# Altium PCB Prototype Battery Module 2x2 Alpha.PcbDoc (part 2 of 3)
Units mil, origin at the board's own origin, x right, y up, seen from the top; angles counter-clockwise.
Board outline 659.45 x 1614.17 mil, 6 copper layers (Component Side, Ground Plane (GND), Inner Layer 1, Inner Layer 2, Power Plane (VCC), Solder Side), stack 51.068 mil thick; 192 components, 101 nets, 859 pads, 497 vias.
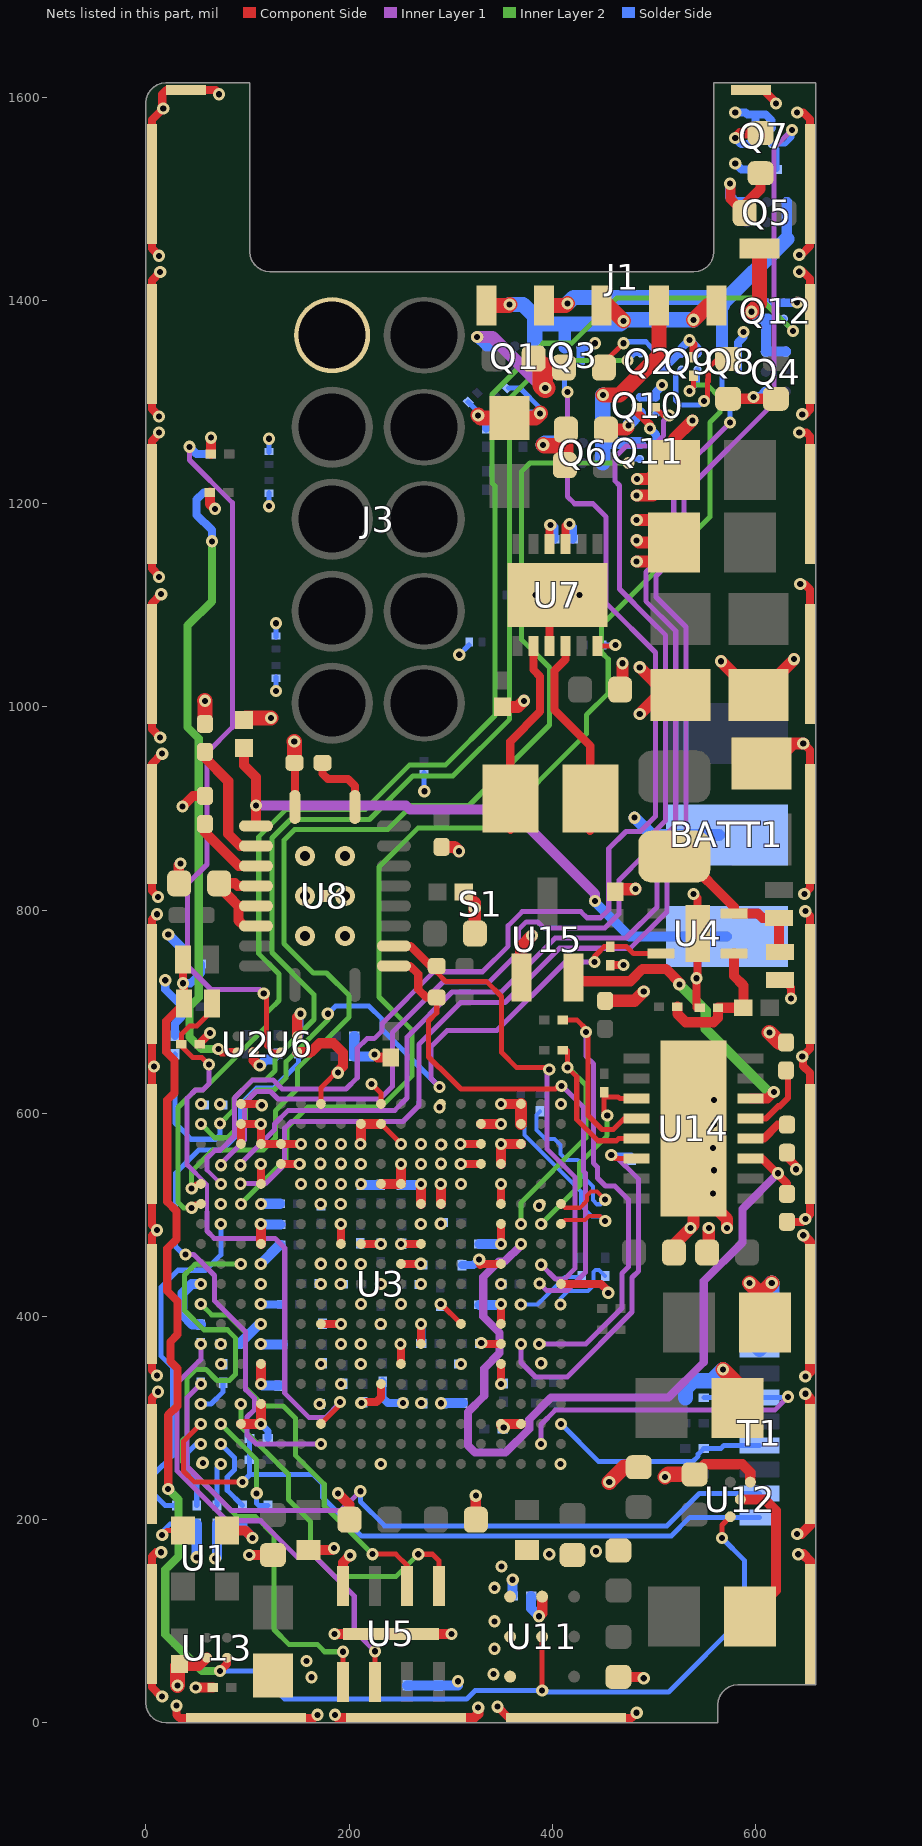
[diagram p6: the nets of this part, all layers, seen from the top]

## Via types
v1: diameter 12, hole 6, Component Side to Solder Side, tented both sides, 490 vias
v2: diameter 19.68, hole 10, Component Side to Solder Side, 6 vias
v3: diameter 12, hole 6, Component Side to Solder Side, 1 vias

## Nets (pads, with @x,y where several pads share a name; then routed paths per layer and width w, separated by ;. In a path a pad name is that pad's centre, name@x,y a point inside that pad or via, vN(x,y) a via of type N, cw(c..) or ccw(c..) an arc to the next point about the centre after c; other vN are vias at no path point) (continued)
CH_STAT1: R42.2 U3.K2 U8.2 | length 520.8
  Component Side w5: R42.2@286.22,714 286.22,699 278,690.78 278,655.42 288.41,645.01 288.99,645.01 310,624 403,624 405,626 409,626 v1(409,627)
  Component Side w8: U8.2@244.09,745.08 259.92,745.08 268,737 268,722 276,714 R42.2@286.22,714
  Inner Layer 1 w5: v1(387.49,432.51) 394.5,425.5 414.73,425.5 432.5,443.27 432.5,541.27 430.5,543.27 430.5,606.35 409.85,627 v1(409,627)
CH_STAT2: R40.2 U3.L2 U8.3 | length 487.9
  Component Side w5: R40.2@286.22,745 286.22,738.78 295.37,729.63 335.37,729.63 350,715 350,660 365,645 v1@395,645
  Component Side w8: U8.3@244.09,764.77 260.23,764.77 280,745 R40.2@286.22,745
  Inner Layer 1 w5: v1(389,451) 403,437 412.09,437 422.5,447.41 422.5,537.12 394.93,564.7 394.93,640.93 v1(397,643)
CLK_19P2MHZ: R52.2 U3.N18 | length 348.6
  Solder Side w5: 23,214.06 18.93,214.06 ; R52.2@30,214.06 R52.2@30,214.06 18.93,214.06 ; v1(73.7,491.14) 73.7,460.7 58.59,445.59 31.59,445.59 15,429 15,361 26,350 26,263 8.41,245.41 8.41,224.58 18.93,214.06
DETECT_RX: R35.2 U3.B13 | length 575.6
  Inner Layer 1 w5: v1(39,461) 47,461 67.52,440.48 67.52,415.48 98,385 98,327.95 ; 98.98,327.48 106.89,319.57 106.89,308.38 99.57,301.07 99.57,283.43 108.32,274.68 v1(172.2,274.68)
  Solder Side w5: 29,479 29,489 ; v1(39,461) 37,461 29,469 29,489 ; R35.2@150,658.94 150,649 126,625 117,625 109,625 93,609 93,582 75,564 52,564 30,542 29,541 29,489
DISC_STAT1_N: R53.2 U3.G3 U14.14 | length 371.9
  Component Side w5: v1@461.5,555.5 464.59,555.5 ; 464.62,555.47 U14.14@482.9,555.47
  Inner Layer 1 w5: v1(369.06,373.11) 369.06,354.85 383.41,340.5 414.64,340.5 478.5,404.36 478.5,438.36 485,444.86 485,535.09 461.09,559 v1(458,559)
  Solder Side w5: v1(458,559) 477.78,559 R53.2@478,558.78
DISC_STAT2_N: R54.2 U3.N2 U14.11 | length 186
  Component Side w5: v1(454,598) 451,601 451,616.22 464.78,616.22 466.47,614.53 U14.11@482.9,614.53
  Inner Layer 2 w5: v1(389,491) 427,529 427,551 454,578 v1(454,598)
DISC_WARN1_N: R50.2 U3.N3 U14.13 | length 332.2
  Component Side w5: R50.2@414.78,662 414.78,645.22 424,636 424,594 445,573 463.22,573 465.38,575.16 U14.13@482.9,575.16
  Inner Layer 2 w5: v1(369.06,491.22) 369.06,512.06 433,576 433,628 414.78,646.22 414,646.22 414,645.26 414.26,645 v1(415,645)
DISC_WARN2_N: R51.2 U3.G2 U14.12 | length 562.3
  Component Side w5: v1(387,373) 388.63,373 U3.G2@388.74,373.11 ; R51.2@414.78,692 424,692 434,682 v1@434,681 ; v1(433,680) v1@434,681 ; U14.12@482.9,594.84 470.84,594.84 460,584 448.91,584 435,597.91 435,680 v1@434,681
  Inner Layer 1 w5: v1(387,373) 433,373 468.5,408.5 468.5,442.5 475,449 475,515 461.5,528.5 452.41,528.5 444.5,536.41 444.5,547 440.5,551 440.5,648.73 433,656.23 v1(433,680)
DONE: R34.1 T1.8 U3.E19 | length 786.8
  Inner Layer 1 w5: 40.52,319.57 40.52,307 ; v1(54.09,333.74) 40.52,320.16 40.52,307 ; v1(211,228) 192,209 83.91,209 40.52,252.39 40.52,307
  Solder Side w5: v1(211,228) 211,218 235,194 245.91,194 310,194 ; 344,194 310,194 ; 559.94,225.94 575,225.94 ; T1.8@593.74,225.94 578,225.94 ; T1.8@604,225.94 578,225.94 ; 310,194 512.86,194 544.8,225.94 575,225.94 ; 575,225.94 578,225.94
EPM_HBA_N: Q3.1 U3.R18 | length 1207.3
  Inner Layer 1 w4: 60.2,544.17 v1(73.78,530.59)
  Inner Layer 1 w5: 60.2,544.17 60.2,555.79 68.11,563.7 73.06,563.7 87.17,577.81 87.17,615.08 105.09,633 125.14,633 134.14,624 197,624 208,635 208,664 217.5,673.5 224.59,673.5 232.5,681.41 232.5,688.5 283.32,739.32 331.32,739.32 356.5,764.5 356.5,784.73 370.27,798.5 428,798.5 434,792.5 447.5,792.5 455.5,800.5 455.5,860.59 472.41,877.5 486.59,877.5 501.5,892.41 501.5,1053.5 453,1102 453,1187 440,1200 422,1200 415,1207 v1(415,1310)
  Solder Side w5: Q3.1@412.13,1338.13 412.13,1312.87 v1(415,1310)
EPM_HBA_P: Q2.1 R59.1 U3.V18 | length 1221.6
  Inner Layer 2 w5: v1(73,590) 73.09,590 86.5,603.41 86.5,614.41 105.09,633 118,633 127,642 127,653.91 165.5,692.41 165.5,716.79 124,758.29 124,871 142.28,889.28 220,889.28 262.72,932 302,932 358,988 358,1303.91 395.09,1341 v1(474,1341)
  Solder Side w5: R59.1@28.54,658.27 28.54,590.46 44.5,574.5 68.5,574.5 73,579 v1(73,590) ; v1(474,1341) 480.87,1347.87 Q2.1@487.13,1347.87
EPM_HBB_N: Q8.1 U3.T17 | length 1141.1
  Inner Layer 1 w5: v1(93,549) 93,550.3 126.57,583.87 126.57,589.52 140.05,603 245,603 257,615 257,675 301.32,719.32 349.68,719.32 402.86,772.5 472.59,772.5 503,802.91 503,865.62 521.5,884.12 521.5,1074.64 492,1104.14 492,1132.91 496.5,1137.41 496.5,1148.98 519.52,1172 519.52,1224.52 v1(575,1280)
  Solder Side w5: Q8.1@567.13,1332.13 567.13,1299.87 575,1292 v1(575,1280)
EPM_HBB_P: Q7.1 R60.1 U3.R17 | length 1488.8
  Inner Layer 1 w5: v1(93.19,530.74) 117.74,530.74 136.57,549.57 136.57,585.38 143.19,592 253,592 268.78,607.78 268.78,667.92 309.86,709 353.5,709 407,762.5 476.73,762.5 513,798.77 513,857 531.5,875.5 531.5,1078.78 502.14,1108.14 502.14,1128.91 506.5,1133.27 506.5,1144.84 529.52,1167.86 529.52,1210.52 618,1299 618,1550 v1(636,1568)
  Solder Side w5: R60.1@621.06,1529 621.06,1548.94 Q7.1@615.87,1554.13 629.13,1554.13 636,1561 v1(636,1568)
EPM_HBC_N: Q11.1 U3.R19 | length 1171.8
  Component Side w5: v1(45,526) 49.59,530.59 53.59,530.59 U3.R19@54.09,530.59
  Inner Layer 2 w5: v1(45,526) 45,543 66,564 115.57,564 127.5,575.93 127.5,602.5 149,624 149,634 149,643.86 200,694.86 200,716 177.78,738.22 164.78,738.22 136,767 136,868.86 146.42,879.28 238,879.28 261.72,903 318,903 397.28,982.28 397.28,1038.72 369.85,1066.15 369.85,1231.85 378,1240 v1(475,1240)
  Solder Side w5: v1(475,1240) 479.13,1244.13 Q11.1@486.13,1244.13
EPM_HBC_P: Q10.1 R61.1 U3.T18 | length 1211.8
  Component Side w5: R61.1@501.06,1295 509.06,1287 v1(515,1287)
  Inner Layer 1 w5: v1(74,549) 74,549.9 73.7,550.2 97.17,573.67 97.17,610.26 108.41,621.5 115,621.5 ; 120.48,621.5 115,621.5 ; 266.42,703.42 274,711 ; 386.59,787.5 385.59,788.5 ; 466,1187 466,1170 ; 492,1090 496,1086 ; v1(515,1287) 509.52,1281.52 509.52,1267 499.52,1257 472.91,1257 461.5,1245.59 461.5,1222.5 466,1218 466,1170 ; 115,621.5 122.5,621.5 130,614 230,614 242.5,626.5 242.5,679.5 274,711 ; 274,711 292.32,729.32 338,729.32 366.5,757.82 366.5,780.59 374.41,788.5 385.59,788.5 ; 385.59,788.5 391.59,782.5 451.64,782.5 465.5,796.36 465.5,829.5 491,855 491,867.77 511.5,888.27 511.5,1070.5 496,1086 ; 466,1170 466,1116 496,1086
  Solder Side w5: Q10.1@501.87,1289.13 512.87,1289.13 v1(515,1287)
EPM_HBD_N: Q12.1 U3.P19 | length 1407.7
  Component Side w5: v1(45,507) 48.91,510.91 U3.P19@54.09,510.91
  Inner Layer 2 w5: v1(45,507) 37,507 31.5,512.5 31.5,605.83 48.5,622.83 55.92,622.83 118.5,685.41 118.5,698.59 123.75,703.84 ; 121.45,701.55 123.75,703.84 ; v1(637,1370) 604.5,1402.5 463.5,1402.5 419,1358 391,1358 340.5,1307.5 340.5,1220.46 343.5,1217.46 343.5,991.5 295,943 259.58,943 215.86,899.28 138.14,899.28 111,872.14 111,757.15 131,737.15 131,711 126.5,706.5 126.41,706.5 123.75,703.84
  Solder Side w5: Q12.1@627.87,1382.13 627.87,1379.13 v1(637,1370)
EPM_HBD_P: Q9.1 R62.1 U3.P17 | length 1183.1
  Component Side w5: v1(535,1311) 539,1315 R62.1@539,1325.94
  Inner Layer 2 w5: v1(93.46,510.91) 137.84,555.28 137.84,569.84 ; 139,571 139,586 159,606 231,606 262,637 262,681.91 229.5,714.41 229.5,842.5 268,881 341,881 433.5,973.5 433.5,992 455,1013.5 455,1047 448.5,1053.5 448.5,1080.5 555,1187 555,1280 565,1290 565,1304.46 552.46,1317 548,1317 541,1317 v1(535,1311)
  Solder Side w5: v1(535,1311) 542.87,1318.87 Q9.1@542.87,1332.13
EPM_REG_EN: R9.1 U3.V19 U4.6 | length 689.8
  Component Side w5: v1(441.43,749) 441.43,754.43 444.36,757.36 451.06,764.06 R9.1@457,764.06 472.94,764.06 479.69,757.31 U4.6@507.17,757.31
  Inner Layer 1 w5: v1(288.95,625.95) 280.5,634.41 280.5,665.5 296.5,681.5 324,681.5 ; 314.41,681.5 324,681.5 ; v1@440,749 v1(441.43,749) 412.91,749 345.41,681.5 324,681.5
  Inner Layer 2 w5: v1(54.09,589.65) 67.74,576 80,576 98,594 98,611.77 109.23,623 126,623 138,635 138,643 ; 138,646.77 138,643 ; v1(179,698) 179,691.77 138,650.77 138,643
  Solder Side w5: v1(179,698) 186.5,705.5 219.59,705.5 232.5,692.59 ; 232.5,690.5 232.5,692.59 ; v1(288.95,625.95) 232.5,682.41 232.5,692.59
EPMA: J1.0 J1.2 J1.4 Q1.4 Q1.5 Q3.4 | length 343.1
  Component Side w15: J1.0@335,1395 357,1395 v1(358,1396) ; J1.2@448.39,1395 455,1395 v1(470,1380) ; v1(539,1381) 553,1395 J1.4@561.77,1395 J1.4@561.5,1394.73
  Solder Side w12: 412,1377 412.13,1376.87 Q3.4@412.13,1353.87
  Solder Side w15: v1(358,1396) 371,1396 382.69,1384.31 ; Q1.4@382.69,1335.16 Q1.5@382.69,1354.84 382.69,1384.31 ; v1(539,1381) 471,1381 v1(470,1380) 467,1377 412,1377 390,1377 382.69,1384.31
EPMB: J1.1 Q5.4 Q5.5 Q8.4 | length 357.9
  Component Side w15: J1.1@391.69,1395 413,1395 v1(415,1397)
  Solder Side w10: 630.69,1460.56 Q5.4@630.69,1477.16 Q5.5@630.69,1496.84
  Solder Side w12: Q8.4@567.13,1347.87 567.13,1395
  Solder Side w15: v1(415,1397) 421,1403 561.13,1403 567.13,1397 ; 566.13,1396 567.13,1395 567.13,1397 ; 630.69,1460.56 567.13,1397
EPMC: J1.3 Q6.4 Q6.5 Q11.4 | length 223.7
  Component Side w15: v1(450,1307) 466.16,1307 505.08,1345.92 J1.3@505.08,1395
  Solder Side w12: Q6.5@449.72,1259.87 Q11.4@486.13,1259.87
  Solder Side w15: Q6.4@449.69,1240.16 Q6.5@449.69,1259.84 449.69,1306.69 v1(450,1307)
EPMD: J1.5 Q4.4 Q4.5 Q12.4 | length 137.2
  Component Side w15: v1(596,1389) 604,1397 J1.5@604,1451
  Solder Side w10: v1(596,1389) 602.87,1382.13 Q12.4@612.13,1382.13 610.16,1380.16 Q4.5@610.16,1349.69 Q4.4@629.84,1349.69
EXO_DETECT_RX: R10.2 U6.A1 | length 731
  Component Side w5: v1(116,718) 118.5,715.5 118.5,699 ; 118.5,703.5 118.5,696 118.5,666.5 124.87,660.13 U6.A1@133.13,660.13
  Inner Layer 1 w5: v1(42.94,1256) 42.94,1243 85,1200.94 85,980 60,955 60,845 41,826 41,745 64,722 112,722 v1(116,718)
  Solder Side w8: v1(42.94,1256) 49.94,1249 R10.2@63.89,1249
EXO_WAKE_RX: R8.2 U2.A1 | length 633.5
  Component Side w8: v1(71.22,663.22) 74.32,660.13 U2.A1@90.13,660.13
  Inner Layer 2 w8: 43,682 43,675 ; 52,666 54.78,663.22 ; v1(64.94,1163) 64.94,1103.94 41,1080 41,980 52,969 52,852 52,714 43,705 43,675 ; v1(71.22,663.22) 54.78,663.22 ; 43,675 54.78,663.22
  Solder Side w8: R8.2@62.89,1211 56.95,1211 49.94,1204 49.94,1189 64.94,1174 v1(64.94,1163)
GND: BATT1.2 C1.1 C2.1 C3.1 C4.1 C5.1 C6.1 C7.1 C8.1 C9.1 C11.1 C12.2 C13.2 C14.2 C15.2 C16.1 C17.2 C18.1 C19.1 C20.1 C21.1 C22.1 C23.1 C24.1 C25.1 C26.1 C27.1 C28.1 C29.1 C30.1 C31.1 C32.1 C33.1 C34.1 C35.1 C36.1 C37.1 C38.1 C39.1 C40.1 C41.1 C42.1 C43.1 C44.1 C45.1 C46.1 C47.1 C48.1 C49.1 C50.1 C51.1 C52.1 C53.1 C57.1 C58.1 C59.1 C60.1 C61.1 C62.1 C63.1 C64.1 C65.1 C66.1 C67.1 C68.1 C69.1 C70.1 C71.1 C72.1 C73.1 C77.1 C78.1 C81.1 C82.1 C94.1 C95.1 D2.1 J3.10 Q2.2 Q2.3 Q3.2 Q3.3 Q7.2 Q7.3 Q8.2 Q8.3 Q9.2 Q9.3 Q10.2 Q10.3 Q11.2 Q11.3 Q12.2 Q12.3 R1.2 R2.1 R5.2 R6.2 R9.2 R14.2 R15.2 R20.1 R21.2 R23.2 R24.2 R25.2 R30.2 R31.2 R32.2 R33.2 R36.2 R37.2 R41.1 R43.1 R45.1 R46.2 R47.2 R48.2 R49.2 R55.2 R56.2 R57.2 R59.2 R60.2 R61.2 R62.2 S1.S T1.1 TVS1.2 TVS2.2 TVS3.2 TVS4.2 TVS5.2 TVS6.2 TVS7.2 TVS8.2 TVS9.2 U1.2 U2.B1 U3.A1 U3.A10 U3.A19 U3.C3 U3.C4 U3.C16 U3.C17 U3.D16 U3.E4 U3.E10 U3.E12 U3.E16 U3.F2 U3.F4 U3.F6 U3.F9 U3.F11 U3.F13 U3.F16 U3.F18 U3.G4 U3.G8 U3.G9 U3.G11 U3.G12 U3.G16 U3.H4 U3.H6 U3.H8 U3.H10 U3.H12 U3.H13 U3.H16 U3.J4 U3.J7 U3.J9 U3.J11 U3.J16 U3.K1 U3.K4 U3.K8 U3.K10 U3.K12 U3.K13 U3.K16 U3.K19 U3.L4 U3.L8 U3.L9 U3.L11 U3.L12 U3.L13 U3.L16 U3.M4 U3.M8 U3.M9 U3.M10 U3.M11 U3.M12 U3.M16 U3.N4 U3.N7 U3.N8 U3.N12 U3.N16 U3.P2 U3.P4 U3.P7 U3.P8 U3.P12 U3.P13 U3.P16 U3.P18 U3.R4 U3.R6 U3.R7 U3.R8 U3.R9 U3.R10 U3.R11 U3.R12 U3.R13 U3.R14 U3.R16 U3.T4 U3.T5 U3.T6 U3.T7 U3.T8 U3.T9 U3.T11 U3.T12 U3.T13 U3.T14 U3.T15 U3.T16 U3.U3 U3.U4 U3.U5 U3.U6 U3.U7 U3.U8 U3.U9 U3.U11 U3.U12 U3.U13 U3.U14 U3.U15 U3.U16 U3.U17 U3.V3 U3.V4 U3.V5 U3.V10 U3.V11 U3.V16 U3.V17 U3.W1 U3.W3 U3.W4 U3.W7 U3.W10 U3.W13 U3.W16 U3.W17 U3.W19 U4.7 U5.4 U5.9 U6.B1 U7.3 U7.9 U7.13 U8.11 U8.21 U11.C1 U11.C2 U11.C3 U12.A3 U13.B1 U14.17 U15.1 | length 8140.9
  Component Side w5: U3.W13@172.2,609.33 172.2,625.2 172.5,625.5 172.59,625.5 180.5,633.41 180.5,633.5 187,640 v1(189,640) ; v1(222,629) 231.26,619.74 U3.W10@231.26,609.33 ; U3.V10@231.26,589.65 v1(250.94,569.96) ; U3.J7@290.39,412.4 U3.H6@310,392.8
  Component Side w7: U3.F18@73.78,353.43 v1(74,353.2)
  Component Side w8: S1.S@5.91,254.92 5.91,319.91 v1(12,326) v1@13,326 ; v1(8,646) v1@8,647 ; v1(11,796) 5.91,790.91 S1.S@5.91,727.36 5.91,662 ; v1@12,342 v1(11,342) 5.91,347.09 S1.S@5.91,412.4 5.91,479.91 v1(11,485) 5.91,490.09 S1.S@5.91,569.88 5.91,644.91 v1@8,647 ; v1(12,813) 5.91,819.09 S1.S@5.91,884.84 5.91,943.91 v1(16,954) ; v1(13,1128) 13,1129 5.91,1136.09 S1.S@5.91,1199.8 5.91,1261.91 13,1269 v1(13,1270) ; v1(13,1286) 5.91,1293.09 S1.S@5.91,1357.28 5.91,1419.91 v1(14,1428) v1@14,1430 ; v1(13,1444) 5.91,1451.09 S1.S@5.91,1514.76 5.91,1577.91 v1(17,1589) 16,1590 16,1603 20.28,1607.28 S1.S@39.37,1607.28 68.72,1607.28 72,1604 v1(72,1603) ; v1(14,970) 5.91,978.09 S1.S@5.91,1042.32 5.91,1101.91 v1(15,1111) ; v1(15,168) 10,168 5.91,163.91 S1.S@5.91,97.44 5.91,35.09 15,26 v1(16,26) ; v1@29,17 v1(30,17) 30,8 33.08,4.92 S1.S@98.43,4.92 165.92,4.92 v1(169,8) ; R41.1@53.06,668 53.06,669.06 v1(63,679) ; U3.U17@93.46,569.96 U3.V17@93.46,589.65 U3.V16@113.15,589.65 U3.U16@113.15,569.96 U3.U15@132.83,569.96 v1(152.52,569.96) ; U3.W17@93.46,609.33 U3.W16@113.15,609.33 114,608.48 v1(114,608) ; U3.R16@113.15,530.59 U3.T16@113.15,550.28 ; U3.T15@132.83,550.28 U3.T14@152.52,550.28 ; R46.2@146.22,945 146.65,944.57 U8.11@146.65,901.58 ; U3.H13@172.2,392.8 191.79,392.8 v1(191.87,392.72) ; v1(191.81,491.22) 191.89,491.15 U3.M12@191.89,471.54 ; U3.M11@211.57,471.54 231.07,471.54 v1(231.17,471.44) ; v1(212,314.94) 213.06,316 227,316 231.26,320.26 U3.E10@231.26,333.74 ; v1(250.69,373.03) 250.94,372.77 U3.F9@250.94,353.43 ; U3.L9@250.94,451.85 270.5,451.85 v1(270.55,451.9) ; v1(250.94,471.54) U3.M8@270.63,471.54 ; U3.G8@270.63,373.11 v1(270.63,392.8) ; v1(290.13,412.4) U3.J7@290.39,412.4 ; U3.T6@310,550.28 U3.T5@329.69,550.28 ; U3.U6@310,569.96 U3.U5@329.69,569.96 ; v1@328,453 v1(328,456) ; v1@329,451 329.85,451.85 U3.L4@349.37,451.85 ; v1(330,374) 330.89,373.11 U3.G4@349.37,373.11 ; v1(346,16) 357.08,4.92 S1.S@413.39,4.92 477.92,4.92 v1(483,10) ; v1(349.37,333.74) U3.F4@349.37,353.43 ; U3.H4@349.37,392.8 v1(349.37,412.48) ; v1(349.37,471.54) U3.N4@349.37,491.22 ; U3.P4@349.37,510.91 v1(349.37,530.59) ; U7.3@397.13,1059.8 397.13,1102.13 U7.13@405,1110 ; U3.K1@408.43,432.17 447.83,432.17 455,425 v1(455,423.33) ; U7.9@412.87,1160.2 413,1160.32 413,1178 415,1180 v1(417,1180) ; R9.2@457,745.94 469.94,745.94 v1(470,746) ; R61.2@482.94,1295 482.94,1290.93 492.21,1281.67 492.33,1281.67 496.02,1277.98 v1(496.02,1274.02) ; v1(535,1361) 539,1357 R62.2@539,1344.06 ; v1(539,816) 543,812 U4.7@543,777 543,735 v1@542,734 ; R14.2@541.94,704 541.94,733.94 v1@542,734 ; v1(542,733) v1@542,734 ; S1.S@595.47,1607.28 607.72,1607.28 620,1595 v1(620,1594) ; D2.1@624,731.22 627.78,731.22 635,724 v1(635,713) ; R55.2@631,493.22 646.22,493.22 v1(649,496) 653.54,500.54 S1.S@653.54,569.88 653.54,640 646.87,646.67 646.87,655.13 v1(646,656) 653.54,663.54 S1.S@653.54,727.36 653.54,794.46 v1(649,799) ; R56.2@631,561.22 631,557 640,548 v1(640,545) ; v1(641,1585) 647,1585 653.54,1578.46 S1.S@653.54,1514.76 653.54,1453.54 645,1445 v1(643,1445) ; v1(643,1270) 650,1270 653.54,1266.46 S1.S@653.54,1199.8 ; v1(643,1428.35) 646.65,1428.35 653.54,1421.46 S1.S@653.54,1357.28 653.54,1292.54 649,1288 v1(646,1288) ; v1(644,1121) 648,1121 653.54,1115.46 S1.S@653.54,1042.32 ; v1(647,964) 653.54,957.46 S1.S@653.54,884.84 653.54,821.54 v1(648,816) ; 5.91,662 5.91,648.91 6,649 v1@8,647 ; 5.91,662 5.91,649.09 v1@8,647
  Component Side w10: C57.1@31,56.01 52.01,56.01 U13.B1@60.16,64.16 ; C43.1@32.72,826.4 32.32,826.8 32.32,844.32 v1(34,846) ; v1(36,902) 46.4,912.4 R36.2@58.07,912.4 ; v1(49,35) C94.1@65.94,35 ; R15.2@62.89,1211 62.89,1200.05 v1(67.94,1195) ; R31.2@63.89,1249 63.89,1264.94 v1(63.94,1265) ; U1.2@79.65,189.56 97.44,189.56 v1(105,182) ; U3.C17@93.46,294.37 U3.C16@113.15,294.37 U3.D16@113.15,314.06 ; v1(101.69,165.32) C60.1@125,165.32 ; U2.B1@105.87,660.13 105.87,652.13 111,647 v1(112,647) ; v1(113.15,333.74) U3.F16@113.15,353.43 ; U3.M16@113.15,471.54 U3.N16@113.15,491.22 ; U6.B1@148.87,660.13 162.13,660.13 171.04,669.04 184.63,669.04 194,659.67 194,646.41 v1@187.29,639.71 ; C16.1@160,170.32 v1@183.32,170.32 ; v1(185.6,87.6) U5.9@241.14,87.6 v1(300.6,87.6) ; v1(186,8) 189.08,4.92 S1.S@255.91,4.92 322.92,4.92 327,9 v1(327,15) ; v1(189,226) 200.32,214.68 C61.1@200.32,200 ; U5.4@193.9,134.84 193.9,157.9 v1(201,165) ; U3.U11@211.57,569.96 U3.V11@211.57,589.65 U3.V10@231.26,589.65 ; v1(225,658) 227.99,655.01 C45.1@241,655.01 ; U3.R10@231.26,530.59 U3.R9@250.94,530.59 v1(250.94,550.28) ; v1(270.59,530.47) 270.63,530.43 U3.P8@270.63,510.91 ; v1(290.17,530.44) 290.32,530.29 U3.P7@290.32,510.91 ; C72.1@324.69,200 v1(324.69,223.68) ; U3.V5@329.69,589.65 v1(349.37,589.65) ; U3.T4@349.37,550.28 v1(349.37,569.96) U3.U3@369.06,569.96 ; v1(349.37,609.33) U3.W3@369.06,609.33 ; v1(352.2,290.6) 349.37,293.43 U3.C4@349.37,294.37 U3.C3@369.06,294.37 ; U3.F2@388.17,354 U3.F2@388.74,353.43 ; C41.1@465,45.32 488.69,45.32 v1(490,44) ; C81.1@540,244.68 549.86,254.55 587.06,254.55 594.84,246.77 U12.A3@594.84,237.05 ; v1(641,186) 645,186 653.54,194.54 S1.S@653.54,254.92 653.54,319.46 v1(649,324) ; v1(642,166) 647,166 653.54,159.46 S1.S@653.54,97.44 ; v1(647,480) 653.54,473.46 ; v1(649,341) 653.54,345.54 S1.S@653.54,412.4 653.54,473.46 ; 653.54,472.46 653.54,473.46
  Component Side w12: R48.2@291,862.22 303.78,862.22 v1(308,858) ; C46.1@312.99,818 323.69,807.31 v1(323.69,802) C42.1@323.69,777 ; C77.1@351,1000.01 366.01,1000.01 v1(372,1006) ; U3.V3@369.06,589.65 U3.W3@369.06,609.33 ; U15.1@369.41,733.6 369.41,764.41 v1(380,775) ; R49.2@452,710.78 480.78,710.78 v1(490,720) ; C9.1@462,817.99 464.51,820.5 481.5,820.5 v1(482,821) ; C50.1@466.69,1017 469,1019.32 v1(469,1043) ; v1(483,1143) 500.6,1143 C8.1@519.6,1162 ; v1(483,1164) 485,1162 C8.1@519.6,1162 ; v1(483,1184) 497.6,1184 C8.1@519.6,1162 ; v1(483,1208) 499,1208 519.6,1228.6 C11.1@519.6,1233 ; v1(483.52,1224.48) 495.48,1224.48 504,1233 C11.1@519.6,1233 ; v1(486,993) 504.6,1011.6 C31.1@513.4,1011.6 ; v1(486,1039) C31.1@513.4,1011.6 ; C48.1@519,463.68 C48.1@519.69,463 519.69,470.68 v1(536,487) 539,490 U14.17@539,529 ; C31.1@526,1011.6 C31.1@513.4,1011.6 ; v1(538,1282) 519.6,1263.6 C11.1@519.6,1233 ; U14.17@539,585 U14.17@539,529 ; C47.1@552.32,463 554,464.68 v1(554,487) ; v1(566,1045) 599.4,1011.6 C53.1@603,1011.6 638,1046.6 v1(638,1047) ; v1(572,487) 572,496 U14.17@539,529 ; C49.1@606,944.4 617.4,944.4 637,964 v1(647,964)
  Component Side w15: v1(31,37) 31,56.01 C57.1@33,58.01 ; v1(58,1006) 58.07,1005.93 R47.2@58.07,983.27 ; R37.2@96.46,987.2 98.25,989 v1(123,989) ; v1(146,966) 146.22,965.78 R46.2@146.22,945 ; v1(327,1287) 329.54,1284.46 C52.1@358,1284.46 383.46,1284.46 v1(388,1289) ; v1(456,237) 470.69,251.68 C82.1@485,251.68 ; v1(511,242) 514,245 514.32,244.68 C81.1@540,244.68 ; v1(568,348) 582.4,333.6 C38.1@582.4,310 C38.1@582.4,330.4 ; v1(594,433) C78.1@609.4,417.6 ; C78.1@609.4,394 C78.1@609.4,417.6 ; v1(613.6,679.64) 623.46,669.78 R57.2@629,669.78 ; v1(616,433) 609.4,426.4 C78.1@609.4,417.6
  Solder Side w5: v1(121,1197.61) TVS8.2@121,1211.21 ; TVS7.2@121,1250.39 v1(121,1264) ; v1(128,1015.61) TVS6.2@128,1029.21 ; TVS5.2@128,1068.79 v1(128,1082.39) ; v1@273.86,917 TVS9.2@273.86,935.35 ; v1(308.38,1051.38) TVS2.2@318,1061 ; TVS4.2@317.19,1300.19 329,1288.37 v1@329,1287 ; TVS3.2@356.81,1313.81 368.19,1313.81 388,1294 v1(388,1289) ; TVS1.2@368.39,1110 v1(383.35,1110)
  Solder Side w7: v1(113.07,294.29) 120.06,287.31 C14.2@120.06,280
  Solder Side w8: v1(19,731) 19,721.94 C32.1@35.94,705 35,704.05 35,695 28.54,688.54 R59.2@28.54,676.38 ; v1(113.07,412.4) 113.47,412 C73.1@133.94,412 ; C5.1@173.69,392.71 v1(191.87,392.72) ; C1.1@211,471.94 211.5,471.44 v1(231.17,471.44) ; C36.1@233,335.94 233,320 238.06,314.94 v1(253,314.94) ; v1(270.63,392.8) 271.12,392.31 C64.1@271.12,373.52 ; C6.1@311.17,450.57 322.57,450.57 v1(328,456) ; v1@328,1288 v1(327,1287) 329,1287 335,1281 R5.2@335,1274.06 ; R6.2@371,1274.06 371,1281 379,1289 v1(388,1289) ; v1(417,1180) 420.06,1176.94 R43.1@420.06,1165 ; Q3.2@427.87,1338.13 Q3.3@427.87,1353.87 437.87,1353.87 v1(442,1358) ; Q10.3@486.13,1304.87 Q10.2@501.87,1304.87 501.87,1309.87 509,1317 v1(508,1317) ; Q2.2@487.13,1332.13 Q2.3@502.87,1332.13 508.69,1332.13 524.44,1347.87 Q9.3@527.13,1347.87 527.13,1353.13 v1(535,1361) 542.87,1353.13 Q9.2@542.87,1347.87 ; v1(496.02,1274.02) 501.87,1268.13 Q11.3@501.87,1259.87 Q11.2@501.87,1244.13 ; v1(580,1535) 586,1529 R60.2@602.94,1529 ; v1(580,1585) 590,1585 592,1583 602,1583 ; Q8.2@582.87,1332.13 Q8.3@582.87,1347.87 582.87,1358.87 588,1364 v1(588,1369) ; Q7.3@600.13,1569.87 600.13,1581.13 602,1583 ; Q12.3@612.13,1397.87 Q12.2@627.87,1397.87 640.87,1397.87 v1(641,1398) ; Q7.2@615.87,1569.87 615.87,1577.13 610,1583 602,1583
  Solder Side w10: v1(22,776) 35.94,762.06 R1.2@35.94,747 ; v1(50,163) R24.2@50,195.94 ; R20.1@54,392.06 45.94,392.06 36,402 36,423 45.09,432.09 v1(54.02,432.09) ; v1(68,162) 69,162 70,163 R25.2@70,195.94 ; R21.2@91.81,373.03 111.5,392.72 v1(113.07,392.72) ; R23.2@95,195.94 95,192 v1(105,182) ; v1(112,647) 118,653 124.06,653 C39.1@130,658.94 ; v1(113.07,373.03) 113.58,372.52 C18.1@134.12,372.52 ; v1(113.07,451.77) 131.82,470.52 C69.1@132.12,470.52 ; v1(113.07,491.14) 113.69,490.52 C28.1@132.12,490.52 ; v1(113.15,333.74) 114.83,332.06 C34.1@131,332.06 ; v1(113.15,510.91) 113.24,511 C71.1@131.94,511 ; C3.1@205.06,676 R2.1@205.06,656 223,656 v1(225,658) ; v1(211.57,530.59) 212.59,529.57 C30.1@231.17,529.57 ; C33.1@251.17,529.57 269.7,529.57 v1(270.59,530.47) ; C13.2@257,36.94 C12.2@288,36.94 306.94,36.94 307,37 v1(307,41) ; v1(290.32,314.63) 290.63,314.94 C63.1@312,314.94 ; C65.1@328.23,411.52 348.41,411.52 v1(349.37,412.48) ; C24.1@328.23,471.52 v1(349.37,471.54) ; R45.1@360.94,125 v1(360.94,140.94)
  Solder Side w12: v1(481,891) 498,874 BATT1.2@564,874
  Solder Side w15: R32.2@530.94,320 530.94,329.02 538.76,336.83 556.83,336.83 v1(568,348) ; T1.1@604,367.68 604,393 616,405 v1(616,433)
  other v1: 163,45 342,48 158,61 343,73 343,100 343,133 350,154 397,166 443,169 185,172 231.18,254.92 408,255 56,256 171,314 271,315 191.89,333.74 172.2,353.43 211.5,353.35 310,353.35 389,354 191.89,373.11 211.5,373.03 231.09,392.63 211.54,412.44 250.91,412.44 113.07,432.09 172.13,431.97 191.74,432.09 231.18,432.03 270.59,432.04 349.37,432.17 172.13,451.91 191.93,451.77 211.5,451.84 270.55,490.98 290.24,491.3 387,509 73.7,510.83 172.09,510.86 191.71,510.83 558,521 309.99,530.44 152.52,530.59 172.2,530.59 191.89,530.59 559,544 113.07,550.2 151.34,550.2 171.88,550.44 192.06,550.44 211.5,550.2 270.59,550.24 290.48,550.44 309.92,550.27 558,566 290.59,569.44 172.2,569.96 192.04,569.88 211.09,569.94 270.63,569.96 309.59,569.94 113.07,589.46 559,589 289,606 54.09,609.33 408.43,609.33 559,613 274,917 426.65,1110
  other v2: 156.49,774.61 195.86,774.61 156.49,813.98 195.86,813.98 156.49,853.35 195.86,853.35
HP_EN: R55.1 U3.M3 U14.3 | length 786.5
  Component Side w8: U14.3@595.1,555.47 606.53,555.47 631,531 R55.1@631,520.78
  Inner Layer 1 w8: v1(369.06,471.54) 369.06,470.01 353.05,454 347.21,454 332,438.79 332,400 348,384 348,364 333,349 333,322 317,306 317,273 324,266 354,266 377.24,289.24 377.24,298.54 398.85,320.15 514.15,320.15 549,355 549,435 587,473 587,506 v1(622,541)
INITN: R26.1 U3.C18 | length 104.7
  Inner Layer 2 w5: v1(73.7,294.29) 109,258.99 v1(109,226)
  Solder Side w5: v1(109,226) 109,216 110.94,214.06 R26.1@120,214.06
NetBATT1_3: BATT1.3 R37.1 U8.12 | length 604.7
  Component Side w10: R37.1@96.46,959.65 96.46,942.54 108.26,930.74 v1(108.26,903) U8.12@108.26,882.88
  Inner Layer 1 w10: v1(108.26,903) 256,903 260,899 359,899 442,816 v1(442,809)
  Solder Side w10: v1(442,809) 441,809 476,774 BATT1.3@571.81,774
NetC10_1: C10.1 R13.2 R14.1 U4.1 | length 144.3
  Component Side w10: R13.2@523.06,705 523.06,697.94 531.33,689.67 558.67,689.67 563.06,694.06 R14.1@563.06,704 C10.1@588.01,704 588.01,725.99 578.83,735.17 U4.1@578.83,757.31
NetC43_2: C43.2 U8.15 U8.16 U8.17 | length 114.7
  Component Side w10: 87.42,826.4 C43.2@72.09,826.4 72.09,823.05 72.91,822.23 81.57,813.57 91,804.14 ; 90,823.82 U8.15@108.26,823.82 ; U8.17@108.26,784.45 96.55,784.45 91,790 91,804.14 ; U8.16@108.26,804.14 91,804.14
NetD1_1: D1.1 D2.2 L2.2 U4.3 | length 165.7
  Component Side w10: L2.2@520,852.63 529.37,852.63 578.83,803.17 U4.3@578.83,796.68 602.32,796.68 606.78,792.22 D1.1@623,792.22 623,759.78 D2.2@624,758.78
NetL5_1: L5.1 U12.B2 | length 154.2
  Component Side w10: U12.B2@585,220 609,220 620,209 620,130.6 L5.1@594.4,105
NetL6_1: L6.1 U7.2 | length 202.2
  Component Side w8: L6.1@359,879 358.63,879.37 L6.1@358.63,910 358.63,966 388,995.37 388,1030 381.38,1036.62 ; 381.38,1043 381.38,1036.62 ; U7.2@381.38,1059.8 381.38,1036.62
NetL6_2: L6.2 U7.4 | length 201.1
  Component Side w8: U7.4@412.87,1059.8 412.87,1046.87 402,1036 402,997 437.37,961.63 L6.2@437.37,910 437.37,878.37 L6.2@437,878
NetQ1_1: Q1.1 R11.2 R12.1 | length 163.1
  Component Side w20: R11.2@381.69,1343 R11.2@390.69,1334 ; v1(393,1314) 390.69,1316.31 R11.2@390.69,1334 ; R12.1@411.32,1334 R11.2@390.69,1334
  Inner Layer 1 w12: v1(326,1364) 341,1364 391,1314 v1(393,1314)
  Solder Side w10: v1(326,1364) 335.16,1354.84 Q1.1@343.32,1354.84
NetQ2_4: Q2.4 R12.2 | length 99.2
  Component Side w5: R12.2@450.69,1334 450.69,1338.69 v1(470,1358)
  Solder Side w5: v1(470,1358) v1@471.41,1359.41 ; 497.66,1353.66 491.9,1359.41 ; Q2.4@502.87,1347.87 502.87,1348.44 491.9,1359.41 ; v1@471.41,1359.41 491.9,1359.41 ; v1@471.41,1359.41 484,1359.41 491.9,1359.41
NetQ4_1: Q4.1 R44.2 R58.1 | length 63.7
  Component Side w10: R58.1@573,1303.32 v1@596.32,1303.32 ; v1(598,1305) v1@596.32,1303.32 ; R44.2@620,1303.31 v1@596.32,1303.31
  Solder Side w10: v1(598,1305) 604.84,1305 Q4.1@610.16,1310.32
NetQ5_1: Q5.1 R16.2 R18.1 | length 112.2
  Component Side w10: v1(575,1515) 575.31,1514.69 575.31,1500 R16.2@589.31,1486 589.31,1494.31 605,1510 R18.1@605,1525.32
  Solder Side w10: v1(575,1515) 575,1502 580.16,1496.84 Q5.1@591.32,1496.84
NetQ6_1: Q6.1 R17.2 R19.1 | length 78.2
  Component Side w15: v1(391,1258) 392,1257 413.32,1257 ; R17.2@412.31,1238 413.32,1239 413.32,1257 ; R19.1@413.32,1273 413.32,1257
  Solder Side w15: v1(391,1258) 392.84,1259.84 Q6.1@410.32,1259.84
NetQ7_4: Q7.4 R18.2 | length 49.5
  Component Side w10: v1(580,1560) 584.69,1564.69 R18.2@605,1564.69
  Solder Side w8: v1(580,1560) 585.87,1554.13 Q7.4@600.13,1554.13
NetQ9_4: Q9.4 R58.2 | length 126.7
  Component Side w5: v1(549.2,1301.16) 549,1300.96 549,1300 552.7,1303.7 552.7,1322.28 553.42,1323 ; 553.42,1320.42 553.42,1323 ; R58.2@573,1342.69 562.69,1342.69 553.42,1333.42 553.42,1323
  Solder Side w5: Q9.4@527.13,1332.13 521.5,1326.5 521.5,1301.5 526,1297 545.04,1297 v1(549.2,1301.16)
NetQ10_4: Q10.4 R19.2 | length 41.9
  Component Side w12: R19.2@452.69,1273 473,1273 475,1275 v1(475,1277)
  Solder Side w12: v1(475,1277) 475,1278 Q10.4@486.13,1289.13
NetR21_1: R21.1 U3.G18
  other v1: 73.7,373.03
NetR23_1: R23.1 U3.B18 | length 78.5
  Solder Side w5: v1(73.7,274.61) 87.2,261.11 87.2,249.16 ; 85.44,247.4 87.2,249.16 ; R23.1@94.5,214.55 R23.1@95,214.06 80,229.06 80,241.96 87.2,249.16
NetR24_1: R24.1 U3.B19 | length 72.3
  Solder Side w5: R24.1@50,214.06 50,237 41,246 41,266 49.61,274.61 v1(54.02,274.61)
NetR25_1: R25.1 U3.A18 | length 42.4
  Solder Side w5: R25.1@70,214.06 70,251.22 v1(73.7,254.92)
NetR30_1: R30.1 U3.D19 | length 35.9
  Solder Side w5: v1(54.02,313.98) 63.98,313.98 76,326 R30.1@76,334.94
NetR33_1: R33.1 U3.W18
  other v1: 73,609
NetR35_1: R35.1 U6.B2 | length 42.4
  Component Side w10: U6.B2@148.87,675.87 148.87,694.87 v1(152,698)
  Solder Side w10: R35.1@150,677.06 v1@150,696
NetR36_1: R36.1 U8.14 | length 72.1
  Component Side w10: R36.1@58.07,884.84 58.07,876.72 91.28,843.51 U8.14@108.26,843.51
NetR39_2: R39.2 U7.6 | length 32.3
  Component Side w5: U7.6@444.5,1059.67 U7.6@444.37,1059.8 460.8,1059.8 v1(462,1061)
  Solder Side w5: R39.2@448.06,1061 v1(462,1061)
NetR43_2: R43.2 U7.10 | length 38.8
  Component Side w8: U7.10@397.13,1160.2 397.13,1176.13 400,1179 v1(398,1179)
  Solder Side w8: v1(398,1179) 400,1179 401.94,1177.06 R43.2@401.94,1165
NetR45_2: R45.2 U11.B1 | length 43.9
  Component Side w10: v1(387,105) 390,108 U11.B1@390,124.37
  Solder Side w10: R45.2@379.06,125 379.06,112.94 v1(387,105)
NetR46_1: R46.1 U8.10 | length 68.4
  Component Side w8: R46.1@173.78,945 173.78,934.22 179,929 199,929 205.71,922.29 U8.10@205.71,901.58
NetR47_1: R47.1 U8.13 | length 122.4
  Component Side w10: R47.1@58.07,955.71 58.07,949.93 81,927 81,875 92.81,863.19 U8.13@108.26,863.19
NetR52_1: R52.1 U1.3 | length 44.6
  Component Side w5: v1(16,185) 18.56,187.56 20.56,189.56 U1.3@36.35,189.56
  Solder Side w5: v1@16,187.12 v1(16,185) 16,188 23.94,195.94 R52.1@30,195.94
NetR56_1: R56.1 U14.4 | length 41.5
  Component Side w8: U14.4@595.1,575.16 608.16,575.16 621.78,588.78 R56.1@631,588.78
NetR57_1: R57.1 U14.5 | length 73.2
  Component Side w6: U14.5@595.1,594.84 610.23,594.84 622.38,607 623.8,607 632,615.2 632,640.22 R57.1@630,642.22
NetU14_6: U14.6 U15.2 | length 287.1
  Component Side w10: U15.2@425.59,733.6 429.19,730 476.63,730 488.63,742 512,742 526,728 v1(525,727) ; U14.6@595.1,614.53 611.53,614.53 v1(618,621)
  Inner Layer 2 w10: v1(525,727) 551,701 551,683 613,621 v1(618,621)
POWER_EN: D3.2 D4.2 R1.1 U11.B2 U12.C1 U13.B2 | length 1548.5
  Component Side w5: v1(390,32) U11.B2@390,85 ; v1(567,182) 567,194.8 U12.C1@575.16,202.95
  Component Side w8: v1(21.91,230.17) 21.91,302.91 31,312 31,348.79 24,355.79 24,375.21 31,382.21 31,415 21,425 21,467 30,476 30,504 21,513 21,613 28,620 28,652.21 20,660.21 20,690.78 D4.2@37.22,708 37.22,727.22 v1(36.42,728.02) D3.2@36.42,751.61 ; v1(73,51) 79.84,57.84 U13.B2@79.84,64.16
  Inner Layer 2 w8: v1(21.91,230.17) 32,220.08 32,163.79 21.21,153 21,153 19,151 19,87 55,51 v1(73,51)
  Solder Side w5: v1(73,51) 109,51 136.56,23.44 315.44,23.44 324,32 v1(390,32) ; v1@391.5,30.5 514.5,30.5 589,105 589,160 v1(567,182)
  Solder Side w8: v1(36.42,728.02) 44,728.02 54.06,738.08 R1.1@54.06,747
POWER_HOLD: D4.1 R41.2 U3.C13 | length 605.2
  Component Side w5: v1(62.02,648.02) 55.04,655 46,655 34.94,666.05 R41.2@34.94,668 34.94,677.94 43,686 50,686 64.78,700.78 D4.1@64.78,708 ; U3.C13@172.2,294.37 191,313.17 v1(191,316)
  Inner Layer 1 w4: 48.92,541.08 60,530 60,503
  Inner Layer 1 w5: 48.92,541.08 40.59,549.41 40.59,614.92 48.67,623 56,623 62,629 v1(62.02,648.02) ; 60,503 60,484.14 67.14,477 127,477 136.65,467.35 136.65,324.58 160.73,300.5 171,300.5 176.59,300.5 191,314.91 v1(191,316)
PROGRAM_N: C14.1 R22.2 T1.7 U3.C19 | length 745.5
  Component Side w5: U3.C19@54.09,294.37 v1(54.02,294.29) 37,277.28 37,248 48,237 82,237 ; v1@91,237 82,237 ; v1(95,237) 82,237
  Solder Side w5: v1(95,237) 101.94,243.94 R22.2@101.94,259 C14.1@101.94,280 ; 102.39,244.5 125,244.5 ; 137.5,244.5 125,244.5 ; 165.59,243.5 170.09,239 ; 580,202.32 T1.7@604,202.32 ; T1.7@593.74,202.32 535.32,202.32 517,184 211.91,184 174,221.91 174,235.09 170.09,239 ; 125,244.5 164.59,244.5 170.09,239
RX_CLK_N: C90.2 U3.J1 | length 71.9
  Solder Side w4: v1(408,412) 408,417.66 415.34,425 435,425 440.33,430.33 440.33,444 442.27,445.94 446.01,445.94 C90.2@452,439.94
RX_CLK_P: C89.2 U3.J3 | length 71.6
  Solder Side w4: v1(369,412) 385.37,412 412.37,439 428.05,439 C89.2@429,439.94
RX_N: C88.2 U3.P1 | length 203.6
  Component Side w4: U3.P1@408.43,510.91 412.27,507.06 427,507.06 430.94,511 431,511 434,514 434,519 438,523 444,523 447,520 v1(452,515)
  Solder Side w4: 384.5,596.44 384.5,590 ; C88.2@388,601.94 384.5,598.44 384.5,590 ; v1(452,515) 447.5,510.5 444,510.5 440,514.5 440,528 430,538 430,549 425,554 414,554 408,560 408,569 402.31,574.69 393.31,574.69 384.5,583.5 384.5,590
RX_P: C87.2 U3.N1 | length 203.6
  Component Side w4: U3.N1@408.43,491.22 412.27,495.06 431.97,495.06 435.91,499 447,499 v1(452,494)
  Solder Side w4: C87.2@369,601.94 372.5,598.44 372.5,589 ; 372.5,596.44 372.5,589 ; v1(452,494) 447.5,498.5 439.03,498.5 428,509.53 428,523 372.5,578.5 372.5,587.5 372.5,589
SPI_FLASH_CLK: R20.2 U3.G19 U5.6 | length 459.3
  Component Side w5: U5.6@225.39,40.35 v1(225.39,70.61)
  Inner Layer 1 w5: 48.16,352.06 54.02,357.92 v1(54.02,373.03) ; 52.5,356.41 46,349.91 30.52,334.42 30.52,323.71 30.52,248.25 79.77,199 113,199 149,163 167,163 205,125 205,91 v1(225.39,70.61)
SPI_FLASH_CS_N: U3.D17 U5.1 | length 347.3
  Component Side w5: v1(268,166) 282,166 288.39,159.61 U5.1@288.39,134.84
  Inner Layer 2 w5: v1(93.39,313.98) 93.39,291.61 140.27,244.73 140.27,219.73 162,198 162,168 186,144 246,144 v1(268,166)
SPI_FLASH_MISO: U3.J19 U5.2 | length 410.1
  Component Side w5: v1(222.89,166.11) 246,166.11 256.89,155.22 U5.2@256.89,134.84
  Inner Layer 2 w5: v1(54.02,412.4) 64.71,401.71 80.29,401.71 98,384 98,329.8 115.8,312 135.09,312 147,300.09 147,263.5 ; 147,278 147,263.5 ; v1(222.89,166.11) 175.5,213.5 175.5,231.59 175.5,235 147,263.5
SPI_FLASH_MOSI: U3.L17 U5.5 | length 654
  Component Side w5: U5.5@193.9,40.35 v1(193.9,70.1)
  Inner Layer 2 w5: v1(93.39,451.77) 48.86,451.77 44.59,447.5 44.5,447.5 38,441 38,406 57,387 80,387 88,379 88,343 82,337 70,337 59,348 49.26,348 40.59,339.33 40.59,329.59 40.52,329.52 40.52,288.62 40.59,288.54 40.59,282.59 36,278 36,257 42.5,250.5 42.5,250.41 50.41,242.5 50.5,242.5 90,203 108,203 126,185 126,92 141,77 169,77 175,71 175.9,70.1 v1(193.9,70.1)
TCK: R32.1 T1.3 U3.B2 | length 374.1
  Inner Layer 1 w5: v1(388.74,274.68) 388.74,293.78 402.83,307.87 618.87,307.87 v1(632,321)
  Solder Side w5: R32.1@549.49,320.43 T1.3@593.74,320.43 ; 576,320.43 T1.3@604,320.43 631.43,320.43 v1(632,321)
TDI: R28.2 T1.5 U3.C1 | length 233.2
  Solder Side w5: v1(408.43,294.37) 445.3,257.5 538.5,257.5 543.56,262.56 543.56,264.51 R28.2@549.06,270 565.81,270 569,273.19 579,273.19 ; T1.5@593.74,273.19 579,273.19 ; T1.5@604,273.19 579,273.19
